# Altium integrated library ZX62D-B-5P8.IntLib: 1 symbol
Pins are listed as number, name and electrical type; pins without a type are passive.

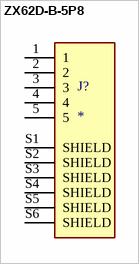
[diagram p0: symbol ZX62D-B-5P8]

## ZX62D-B-5P8
designator J?
USB - micro B USB 2.0 Receptacle Connector 5 Position Surface Mount, Right Angle; Through Hole; MF: Hirose Connector; MP: ZX62D-B-5P8
footprint HRS_ZX62D-B-5P8
pins: 1, 2, 3, 4, 5, S1 SHIELD, S2 SHIELD, S3 SHIELD, S4 SHIELD, S5 SHIELD, S6 SHIELD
